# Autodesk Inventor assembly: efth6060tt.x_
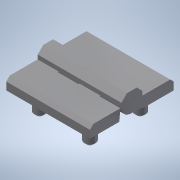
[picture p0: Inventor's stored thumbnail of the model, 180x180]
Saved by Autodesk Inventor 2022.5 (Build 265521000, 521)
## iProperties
Part Number: efth6060tt.x_
Material: 一般
Document SubType Name: Assembly
Designer: ImaoCorp
Sending System: SOLIDWORKS 2017-2017317
MC: AMD64
MC_MODEL: Intel64 Family 6 Model 60 Stepping 3, GenuineIntel
OS: Windows_NT
FRU: Parasolid Version 29.0, build 201,  4-17-2017
FORMAT: text
GUISE: transmit
KEY: efth6060tt
FILE: efth6060tt.x_t
DATE: Mon May 13 14:22:04 2019
Author: ImaoCorp
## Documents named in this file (4)
- X:\14_SW2022-Inv2022\00_全2023-1023新製品(TCC)まで\e\efth6060tt\EFTH6060TT.iam
- X:\14_SW2022-Inv2022\00_全2023-1023新製品(TCC)まで\e\efth6060tt\efth6060tt_01.ipt
- X:\14_SW2022-Inv2022\00_全2023-1023新製品(TCC)まで\e\efth6060tt\efth6060tt_02.ipt
- X:\14_SW2022-Inv2022\00_全2023-1023新製品(TCC)まで\e\efth6060tt\efth6060tt_03.ipt
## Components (3 placed, 3 different names)
1. efth6060tt_01
2. efth6060tt_02
3. efth6060tt_03
